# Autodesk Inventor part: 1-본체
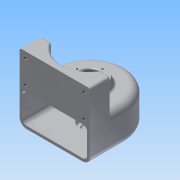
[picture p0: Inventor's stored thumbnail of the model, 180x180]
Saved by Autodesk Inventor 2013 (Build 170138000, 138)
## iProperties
Created: 2015-02
Part Number: 1-본체
Material: 알루미늄 6061
Document SubType Name: Modeling
Designer: Administrator
Density: 2.40731 g/cm^3
Mass: 511.244 g
Surface Area: 706.56 cm^2
Volume: 212.371 cm^3
Author: Administrator
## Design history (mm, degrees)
sketch "스케치1"
  geometry: L1 (-50, -50)-(50, -50); L2 (50, -50)-(50, 0); L3 (-50, 0)-(-50, -50); A1 r 50 centre (0, 0) between (50, 0) and (-50, 0); 1 further point
  constraints: 6 end point, 2 point on circle, 2 tangent, 1 centre point, 1 coincident, 1 horizontal, 1 parallel, 1 perpendicular
  dimensions: "d0" = 50 distance from line of L1 point (0, 0); "d1" = 50 radius of A1
extrude "돌출1" new body sketch "스케치1" distance "d2" = 50; taper "d3" = 0 deg
fillet "모깎기1" dims "d4" = 10
feature "쉘1" dims "d5" = 4
node "작업 평면1"
sketch "스케치2"
  geometry: C1 r 20 at (0, 0); 1 further point
  constraints: 1 centre point, 1 coincident
  dimensions: "d7" = 40 diameter of C1
extrude "돌출2" join sketch "스케치2" stored distance "d9" = 50; taper "d10" = 0 deg
hole "구멍1" diameter "d13" = 20; stored, may be unused: countersink angle "d17" = 90 deg, drill point angle "d19" = 0 deg; dims "d11" = 10, "d12" = 10, "d14" = 6, "d15" = 28, "d16" = 8, "d18" = 10
sketch "스케치4"
  geometry: C1 r 25 at (0, 0); A1 r 40 centre (0, 0) between (40, 0) and (-40, 0) reference
  constraints: 1 centre point, 1 coincident
  dimensions: "d21" = 50 diameter of C1
extrude "돌출3" join sketch "스케치4" distance "d23" = 10; taper "d24" = -20 deg
hole "구멍2" diameter "d27" = 20; stored, may be unused: countersink angle "d31" = 90 deg, drill point angle "d33" = 0 deg; dims "d25" = 10, "d26" = 10, "d28" = 6, "d29" = 28, "d30" = 10, "d32" = 10
node "작업 평면4"
sketch "스케치7"
  geometry: L1 (50, -20)-(34.641, -20); L2 (-50, -20)-(-34.641, -20); L3 (-40, -50)-(-50, -50) reference; L4 (-50, -20)-(-50, -50); L5 (50, -50)-(50, -20); L6 (-50, -50)-(50, -50); A1 r 40 centre (0, 0) between (-34.641, -20) and (34.641, -20); 1 further point
  constraints: 10 end point, 2 collinear, 2 equal length, 2 point on circle, 1 centre point, 1 coincident, 1 horizontal, 1 perpendicular
  dimensions: "d39" = 40 radius of A1; "d41" = 30 distance between parallel lines of L3 L2; "d42" = 100 distance of L1.start L2.start
extrude "돌출4" join sketch "스케치7" stored distance "d43" = 10; taper "d44" = 0 deg
sketch "스케치8"
  geometry: L1 (-10, 95)-(90, 95) reference; L2 (81.75, 53)-(-1.75, 53); L3 (-1.75, 53)-(-1.75, 86); L4 (-1.75, 86)-(81.75, 86); L5 (81.75, 86)-(81.75, 53); 7 further points
  constraints: 8 end point, 4 coincident, 2 midpoint, 2 parallel, 1 horizontal, 1 perpendicular, 1 vertical alignment
  dimensions: "d45" = 83.5 distance of L3.end L4.end; "d47" = 9 distance between parallel lines of L4 L1; "d48" = 33 distance of L2.end L3.end
hole "구멍3" sketch "스케치8" at (-1.75, 86), (-1.75, 53), (81.75, 53), (81.75, 86) diameter "d49" = 5.134; stored, may be unused: countersink angle "d53" = 90 deg, drill point angle "d55" = 118 deg; dims "d50" = 10, "d51" = 28, "d52" = 10, "d54" = 13
sketch "스케치9"
  geometry: C1 r 14 at (0, 0) reference; 1 further point
  constraints: 1 vertical alignment
  dimensions: "d56" = 18 distance of point (0, 18) C1.centre
hole "구멍4" sketch "스케치9" at (0, 18) diameter "d57" = 2.459; stored, may be unused: countersink angle "d61" = 90 deg, drill point angle "d63" = 118 deg; dims "d58" = 6, "d59" = 28, "d60" = 10, "d62" = 9
fillet "모깎기2" dims "d67" = 0.3, "d68" = 3
fillet "모깎기3" dims "d69" = 3
chamfer "모따기1" distance "d70" = 1; stored, may be unused: second distance "d71" = 2, angle "d72" = 45 deg
node "작업 평면5"
sketch "스케치10"
  geometry: L1 (17, -9)-(-17, -9) reference; 2 further points
  constraints: 1 vertical alignment, 1 other
  dimensions: "d73" = 25 distance from line of point (0, 16) L1
feature "엠보싱1" sketch "스케치10" dims "d15" = 28, "d74" = 0.5, "d75" = 0
node "솔리드1"
pattern_circular "원형 패턴1" dims angle "d65" = 360 deg
other parameters: "d6" = 9, "d38" = -95
